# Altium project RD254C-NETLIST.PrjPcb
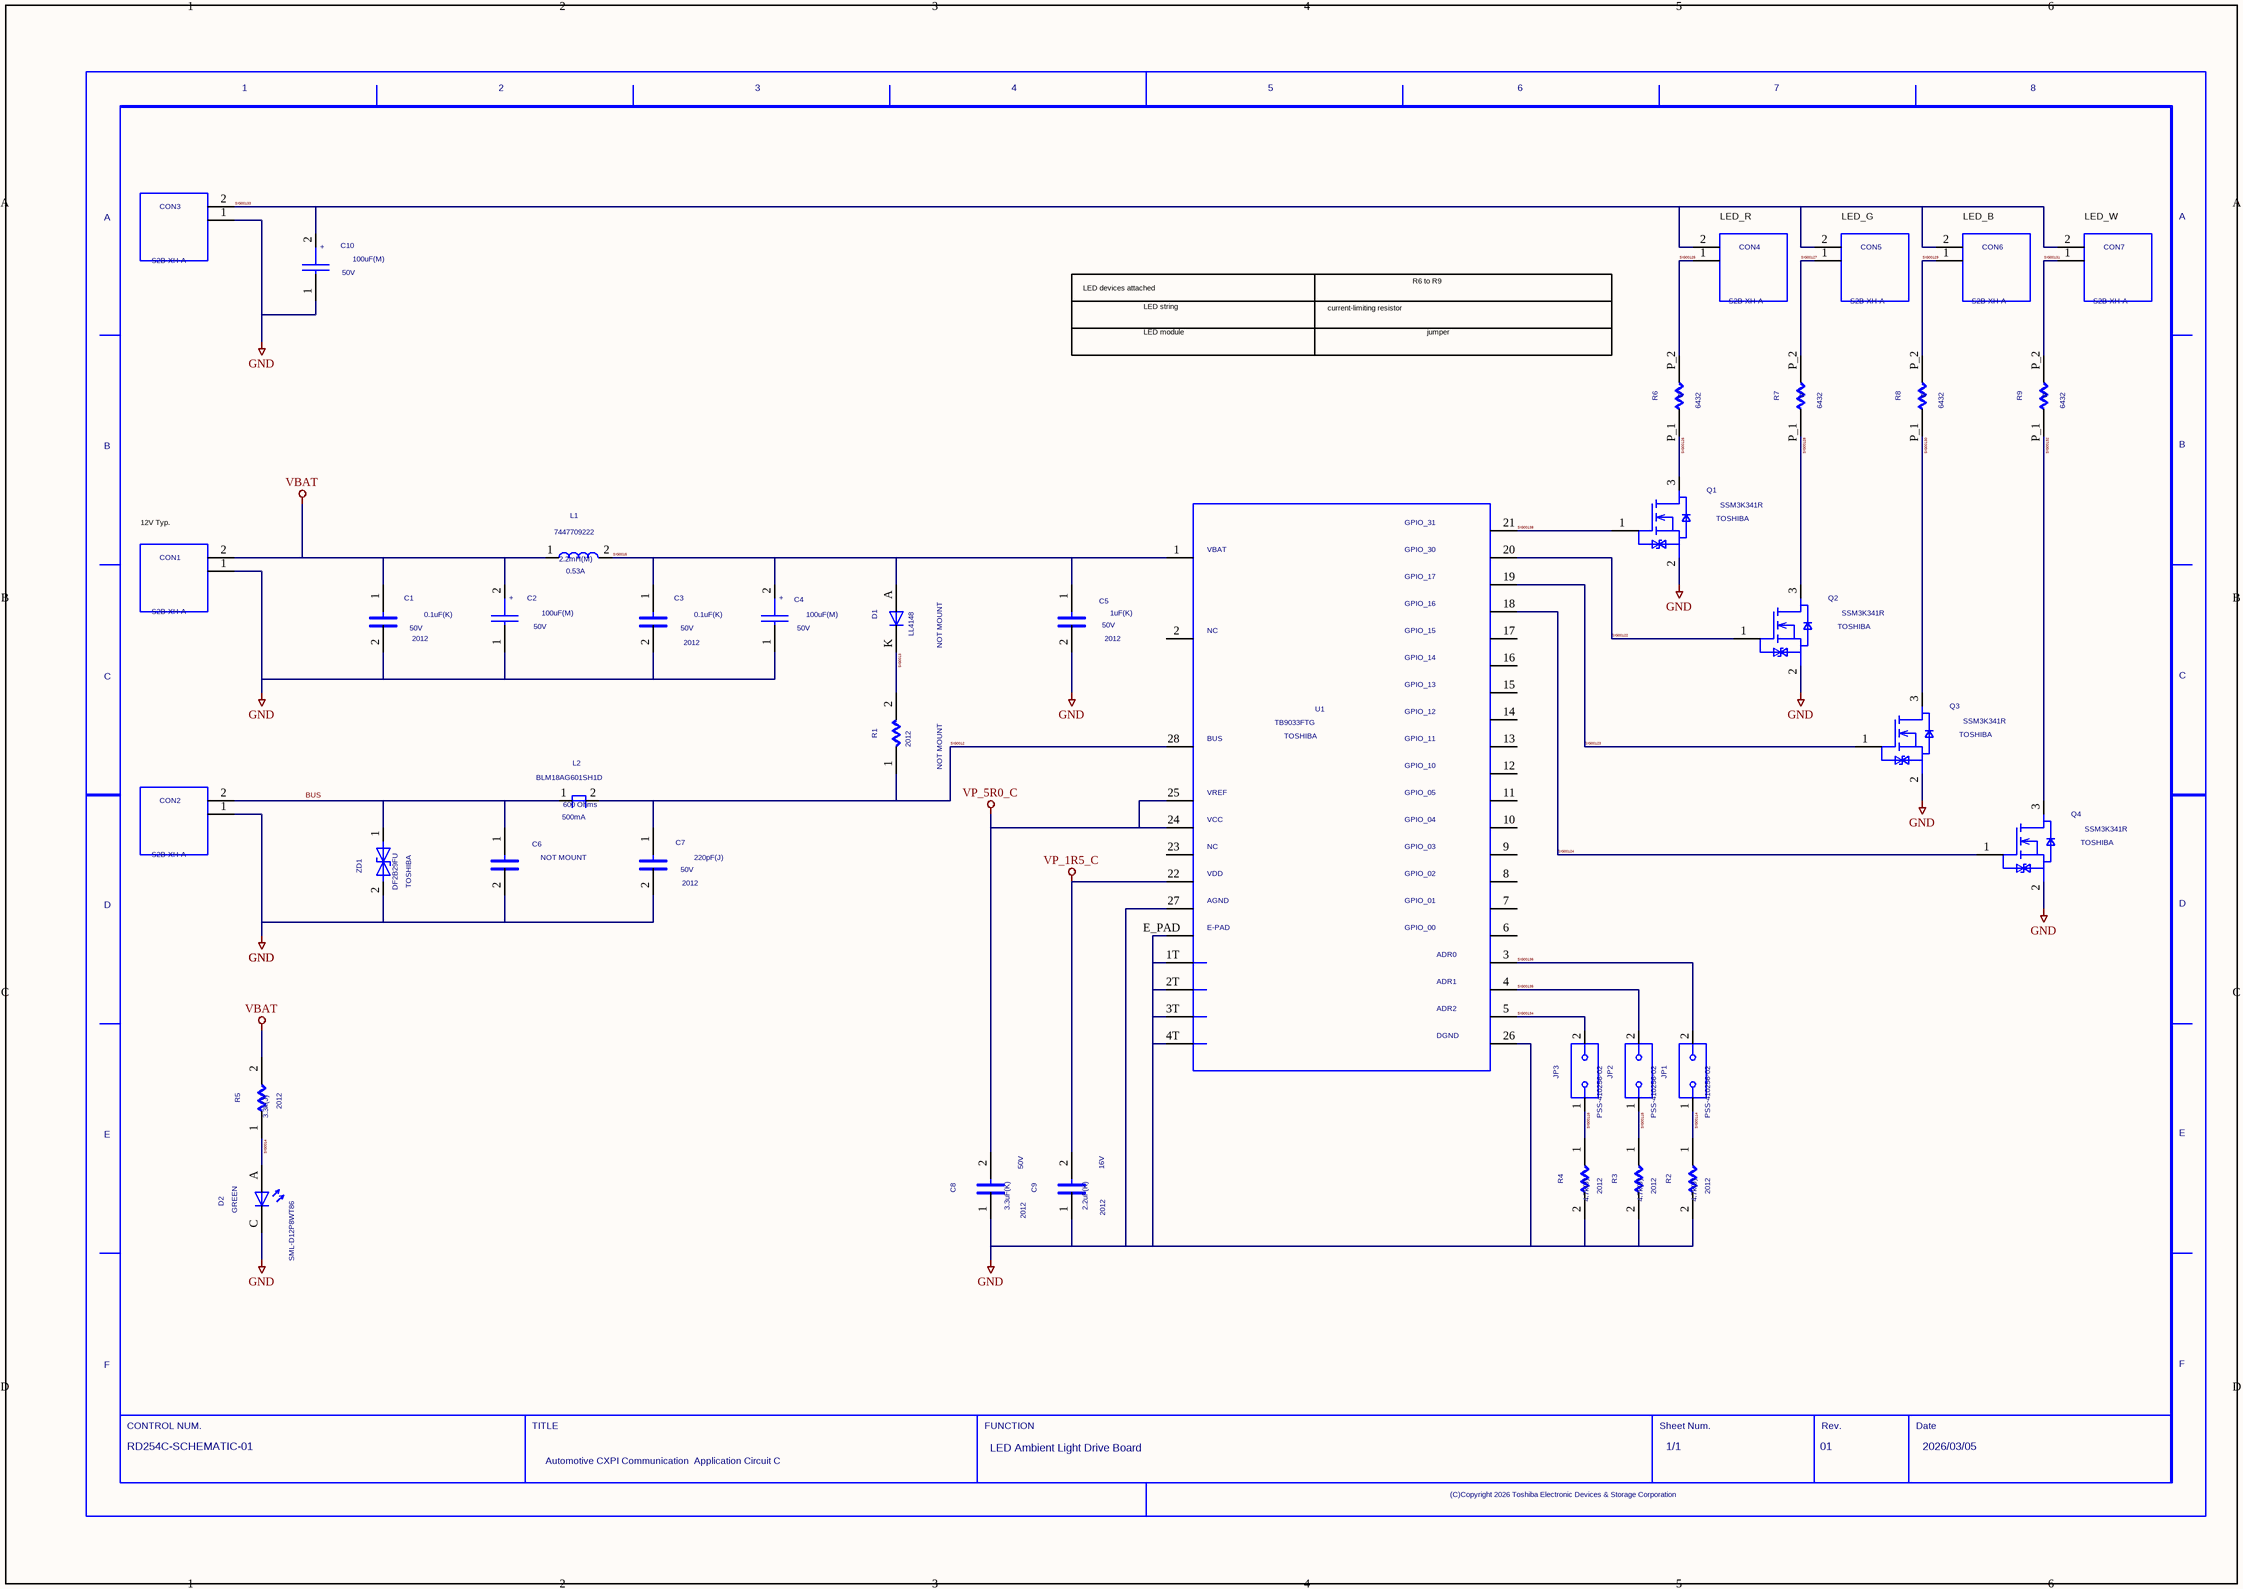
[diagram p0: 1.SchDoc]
1 sheet, 40 parts. Net scope: global (net labels, ports and power ports of the same name join across sheets).

## Sheet 1.SchDoc
size 420 x 297 mm

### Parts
C1  VAL1: 0.1uF(K)  VAL2: 50V  SIZECODESMD: 2012  (hidden comment: C)
C2  VAL1: 100uF(M)  VAL2: 50V  (hidden comment: CP)
C3  VAL1: 0.1uF(K)  VAL2: 50V  SIZECODESMD: 2012  (hidden comment: C)
C4  VAL1: 100uF(M)  VAL2: 50V  (hidden comment: CP)
C5  VAL1: 1uF(K)  VAL2: 50V  SIZECODESMD: 2012  (hidden comment: C)
C6  NOTMOUNT: NOT MOUNT  (hidden comment: C)
C7  VAL1: 220pF(J)  VAL2: 50V  SIZECODESMD: 2012  (hidden comment: C)
C8  VAL1: 3.3uF(K)  VAL2: 50V  SIZECODESMD: 2012  (hidden comment: C)
C9  VAL1: 2.2uF(K)  VAL2: 16V  SIZECODESMD: 2012  (hidden comment: C)
C10  VAL1: 100uF(M)  VAL2: 50V  (hidden comment: CP)
CON1  S2B-XH-A
CON2  S2B-XH-A
CON3  S2B-XH-A
CON4  S2B-XH-A
CON5  S2B-XH-A
CON6  S2B-XH-A
CON7  S2B-XH-A
D1  NOTMOUNT: NOT MOUNT  VAL3: LL4148  (hidden comment: D)
D2  VAL2: GREEN  VAL3: SML-D12P8WT86  (hidden comment: LED)
JP1  PSS-410256-02
JP2  PSS-410256-02
JP3  PSS-410256-02
L1  VAL1: 2.2mH(M)  VAL2: 0.53A  VAL3: 7447709222  (hidden comment: L)
L2  VAL2: 500mA  VAL3: BLM18AG601SH1D  VAL1: 600 Ohms  (hidden comment: FB)
Q1  USERCOMPTEXT3: TOSHIBA  (hidden comment: SSM3K341R)
Q2  USERCOMPTEXT3: TOSHIBA  (hidden comment: SSM3K341R)
Q3  USERCOMPTEXT3: TOSHIBA  (hidden comment: SSM3K341R)
Q4  USERCOMPTEXT3: TOSHIBA  (hidden comment: SSM3K341R)
R1  NOTMOUNT: NOT MOUNT  SIZECODESMD: 2012  (hidden comment: R)
R2  VAL1: 4.7k(J)  SIZECODESMD: 2012  (hidden comment: R)
R3  VAL1: 4.7k(J)  SIZECODESMD: 2012  (hidden comment: R)
R4  VAL1: 4.7k(J)  SIZECODESMD: 2012  (hidden comment: R)
R5  VAL1: 3.3k(J)  SIZECODESMD: 2012  (hidden comment: R)
R6  VAL1: 0  SIZECODESMD: 6432  (hidden comment: R)
R7  VAL1: 0  SIZECODESMD: 6432  (hidden comment: R)
R8  VAL1: 0  SIZECODESMD: 6432  (hidden comment: R)
R9  VAL1: 0  SIZECODESMD: 6432  (hidden comment: R)
U1  VAL3: TB9033FTG  USERCOMPTEXT3: TOSHIBA  (hidden comment: TB9033FTGIC_VERB)
U?  DATE: 2026/03/05  DRAWINGNUMBER: RD254C-SCHEMATIC-01  TITLE: Automotive CXPI Communication / Application Circuit C  FUNCTION: LED Ambient Light Drive Board  SHEETNUMBER: 1/1  REVISION: 01  (hidden comment: WAKU_DEF100)
ZD1  USERCOMPTEXT3: TOSHIBA  VAL3: DF2B29FU  (hidden comment: ZDB)

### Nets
GND: C1.2 C2.1 C3.2 C4.1 C5.2 C6.2 C7.2 C8.1 C9.1 C10.1 CON1.1 CON2.1 CON3.1 D2.C Q1.2 Q2.2 Q3.2 Q4.2 R2.2 R3.2 R4.2 U1.1T U1.2T U1.3T U1.4T U1.26 U1.27 U1.E_PAD ZD1.2
VBAT: C1.1 C2.2 CON1.2 L1.1 R5.2
VP_1R5_C: C9.2 U1.22
VP_5R0_C: C8.2 U1.24 U1.25
BUS: C6.1 CON2.2 L2.1 ZD1.1
SIG0012: C7.1 L2.2 R1.1 U1.28
SIG0013: D1.K(C) R1.2
SIG0014: D2.A R5.1
SIG0015: C3.1 C4.2 C5.1 D1.A L1.2 U1.1
SIG00114: JP1.1 R2.1
SIG00115: JP2.1 R3.1
SIG00116: JP3.1 R4.1
SIG00122: Q2.1 U1.20
SIG00123: Q3.1 U1.19
SIG00124: Q4.1 U1.18
SIG00125: CON4.1 R6.P_2
SIG00126: Q1.3 R6.P_1
SIG00127: CON5.1 R7.P_2
SIG00128: Q2.3 R7.P_1
SIG00129: CON6.1 R8.P_2
SIG00130: Q3.3 R8.P_1
SIG00131: CON7.1 R9.P_2
SIG00132: Q4.3 R9.P_1
SIG00133: C10.2 CON3.2 CON4.2 CON5.2 CON6.2 CON7.2
SIG00134: JP3.2 U1.5
SIG00135: JP2.2 U1.4
SIG00136: JP1.2 U1.3
SIG00138: Q1.1 U1.21

Not connected (* = marked no-connect by the designer): U1 2 6 7 8 9 10 11 12 13 14 15 16 17 23

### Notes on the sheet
- (near CON4) LED_R
- (near CON5) LED_G
- (near CON6) LED_B
- (near CON7) LED_W
- LED devices attached
  to CON4 to CON7
- LED string
- current-limiting resistor
- R6 to R9
- LED module
- jumper
- (near CON1) 12V Typ.
  6V to 16V

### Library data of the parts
C1 C3 C6 C7 = C: OriginalSymbolOrigin: (2540,7620); SAVECOUNT: 0
C2 C4 C10 = CP: SAVEAREA0: -1450,-153,20294,13055; SAVECOUNT: 52; TIME: 15:02:55; UPDATEUSER: fukuda-y; UPDATETIME: 16:13:42; OriginalSymbolOrigin: (2540,10160); COMP: C
C5 = C: NOTMOUNT: MOUNT; OriginalSymbolOrigin: (2540,7620); SAVECOUNT: 0
C8 C9 = C#1: OriginalSymbolOrigin: (2540,7620); CaptureCellPackProp: C##1; SAVECOUNT: 0
CON1-CON7 = S2B-XH-A: SAVEAREA0: -63393,-16950,474261,314592; TIME: 14:30:25; UPDATEUSER: t5459927; UPDATETIME: 11:18:03; SAVECOUNT: 20; OriginalSymbolOrigin: (0,12700)
D1 = D: SAVEAREA0: -225,-91,12804,7836; SAVECOUNT: 3; TIME: 14:49:55; UPDATEUSER: 19870035; UPDATETIME: 14:20:16; OriginalSymbolOrigin: (5080,5080)
D2 = LED: SAVEAREA0: -6799,-183,19247,15664; TIME: 14:49:55; UPDATEUSER: fukuda-y; UPDATETIME: 13:54:07; SAVECOUNT: 4; OriginalSymbolOrigin: (5080,7620)
JP1-JP3 = PSS-410256-02: SAVEAREA0: -63393,-16950,474261,314592; TIME: 14:30:25; UPDATEUSER: t5459927; UPDATETIME: 18:56:33; SAVECOUNT: 22; OriginalSymbolOrigin: (2540,5080)
L1 = L: OriginalSymbolOrigin: (2540,5080); SAVECOUNT: 0
L2 = FB: SAVEAREA0: -63393,-16950,474261,314592; TIME: 14:30:25; UPDATEUSER: t5459927; UPDATETIME: 11:02:03; SAVECOUNT: 20; OriginalSymbolOrigin: (7620,7620)
Q1-Q4 = SSM3K341R: SAVEAREA0: -63393,-16950,474261,314592; TIME: 14:30:25; UPDATEUSER: t5459927; UPDATETIME: 12:01:19; SAVECOUNT: 22; OriginalSymbolOrigin: (5080,12700)
R1 = R: OriginalSymbolOrigin: (5080,5080); SAVECOUNT: 0
R2-R4 = R: VAL2: 250mW; OriginalSymbolOrigin: (5080,5080); SAVECOUNT: 0
R5 = R#1: VAL2: 250mW; OriginalSymbolOrigin: (5080,5080); CaptureCellPackProp: R##1; SAVECOUNT: 0
R6-R9 = R#2: VAL2: 2W; OriginalSymbolOrigin: (5080,5080); CaptureCellPackProp: R##2
U1 = TB9033FTGIC_VERB: SAVEAREA0: -63393,-16950,474261,314592; TIME: 14:30:25; UPDATEUSER: t5459927; UPDATETIME: 17:47:26; SAVECOUNT: 27; OriginalSymbolOrigin: (5080,106680)
U? = WAKU_DEF100: PLOTTIME: HH:MM; SAVEAREA0: -63393,-16950,474261,314592; TIME: 14:30:25; UPDATEUSER: t5459927; UPDATETIME: 17:21:36; SAVECOUNT: 5; OriginalSymbolOrigin: (10160,284480); SHTSAVECOUNT: 56
ZD1 = ZDB: SAVEAREA0: -4630,-153,17114,13055; TIME: 14:49:55; UPDATEUSER: fukuda-y; UPDATETIME: 08:22:19; SAVECOUNT: 6; OriginalSymbolOrigin: (2540,5080)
